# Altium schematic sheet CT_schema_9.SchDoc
size 287 x 160 mm
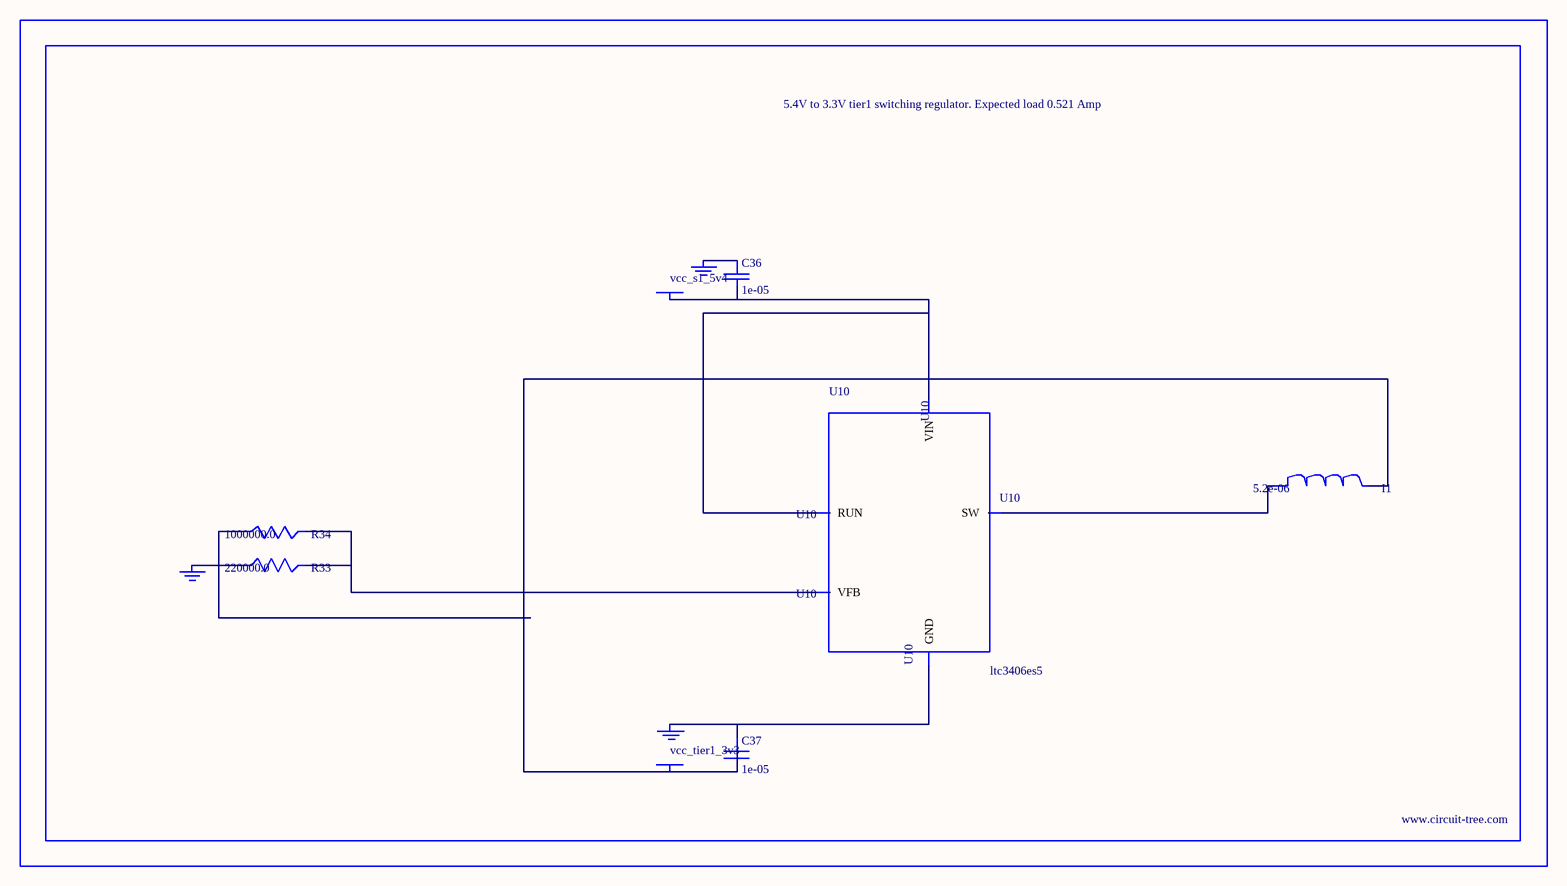
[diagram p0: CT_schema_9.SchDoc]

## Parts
BORDER8  (no value)
C36  1e-05  [C0805]
C37  1e-05  [C0805]
GND_INSTANCE_8_0  (no value)
GND_INSTANCE_8_1  (no value)
GND_INSTANCE_8_2  (no value)
I1  5.2e-06  [DR1040]
POWER_INSTANCE_8_0  vcc_tier1_3v3
POWER_INSTANCE_8_1  vcc_s1_5v4
R33  220000.0  [R0603]
R34  1000000.0  [R0603]
U10  ltc3406es5  [TSOT-23-5]

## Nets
NetC36_1: C36.1 GND_INSTANCE_8_1.0(GND)
NetC36_2: C36.2 POWER_INSTANCE_8_1.0(PWR) U10.1(RUN) U10.4(VIN)
NetC37_1: C37.1 GND_INSTANCE_8_0.0(GND) U10.2(GND)
NetC37_2: C37.2 I1.2 POWER_INSTANCE_8_0.0(PWR) R34.1
NetGND_INSTANCE_8_2_0: GND_INSTANCE_8_2.0(GND) R33.1
NetI1_1: I1.1 U10.3(SW)
NetR33_2: R33.2 R34.2 U10.5(VFB)

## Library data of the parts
BORDER8 = BORDER_PAGE8
C36 C37 = C0805C106K8RACTU
GND_INSTANCE_8_0-GND_INSTANCE_8_2 = GND
I1 = DR1040-5R2-R
POWER_INSTANCE_8_0 POWER_INSTANCE_8_1 = PWR
R33 = RC0603JR-07220KL
R34 = RC0603JR-071ML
